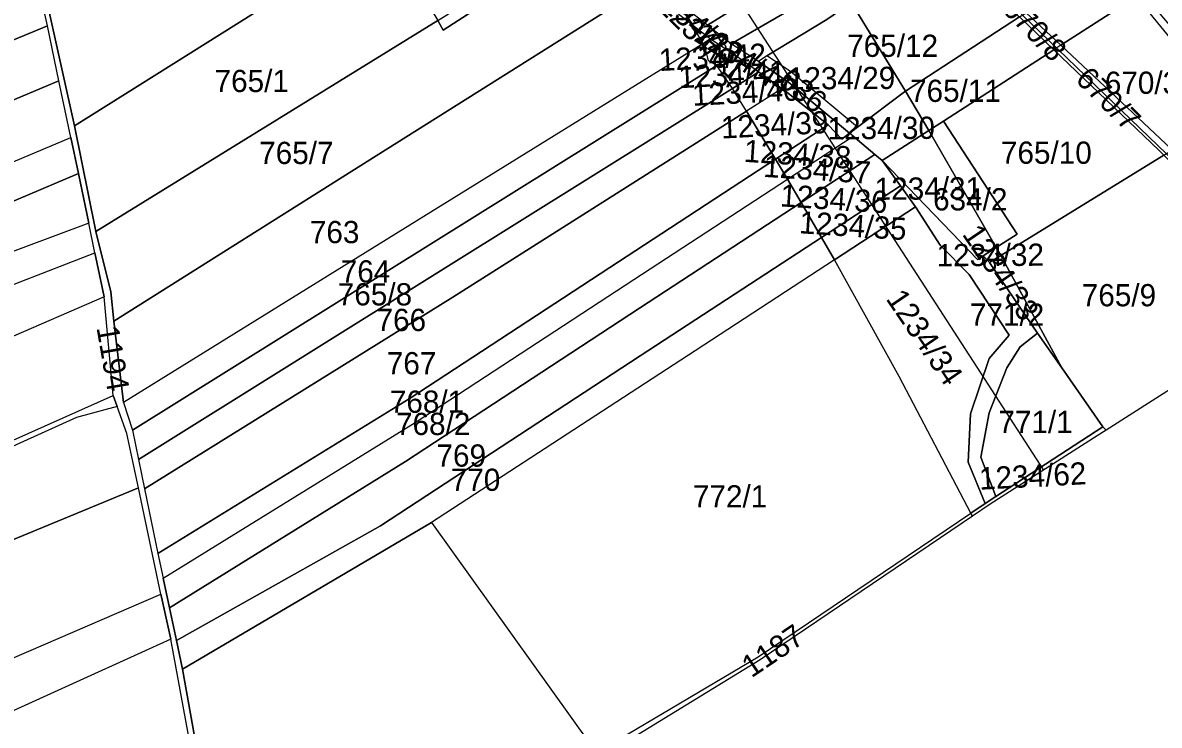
# Model space of a CAD drawing. Extents: x -623250 to -619626, y -1079612 to -1075424.
# Drawn here: x -620640 to -620129, y -1077297 to -1076980 of the extents above; entities that cross this region are included whole.
import ezdxf

# ---------------------------------------------------------------- set-up
doc = ezdxf.new("R2010")
doc.units = 0
for name, color, linetype in [('Dálnice a přivaděč', 7, 'Continuous'), ('Hranice převzatá (KoPÚ Hrušová)', 7, 'Continuous'), ('Parcela nároku', 7, 'Continuous'), ('Parcelní číslo', 7, 'Continuous'), ('Vodní toky', 7, 'Continuous')]:
    doc.layers.add(name, color=color, linetype=linetype)

msp = doc.modelspace()

# ---------------------------------------------------------------- linework, layer by layer
at = {"layer": 'Dálnice a přivaděč'}
msp.add_lwpolyline([(-621211.3, -1075762.42), (-621042.48, -1076053.84), (-620715.11, -1076495.7), (-620421.91, -1076809.46), (-620180.94, -1077181.74)], dxfattribs=at)
at = {"layer": 'Hranice převzatá (KoPÚ Hrušová)'}
msp.add_lwpolyline([(-620097.76, -1077128.63), (-620152.81, -1077163.77), (-620156.83, -1077166.34), (-620205.06, -1077197.13), (-620212.99, -1077202.5), (-620227.43, -1077212.27), (-620308.56, -1077267.13), (-620370.5, -1077305.13)], dxfattribs=at)
at = {"layer": 'Parcela nároku'}
for points in [[(-620119.98, -1076986.55), (-620149.91, -1076951.14), (-620165.48, -1076931.43), (-620186.12, -1076902.91), (-620210.08, -1076879.13), (-620234.82, -1076852.68), (-620272.81, -1076807.82), (-620281.18, -1076791.72), (-620287.52, -1076789.59), (-620286.26, -1076791.95), (-620275.61, -1076809.03), (-620263.77, -1076823.1), (-620250.84, -1076838.48), (-620237.34, -1076854.52), (-620222.38, -1076870.61), (-620212.62, -1076881.11), (-620205.93, -1076888.11), (-620198.43, -1076895.95), (-620188.91, -1076904.44), (-620182.36, -1076913.38), (-620153.45, -1076952.88), (-620139.36, -1076968.66), (-620122.17, -1076989.65)], [(-620564.8, -1077306.77), (-620573.82, -1077257.79), (-620578.2, -1077237.62), (-620588.31, -1077189.72), (-620593.55, -1077165.29), (-620597.96, -1077153.14), (-620599.73, -1077148.14), (-620603.79, -1077103.85), (-620607.96, -1077083.92), (-620610.74, -1077070.63), (-620615.34, -1077048.34), (-620618.82, -1077032.03), (-620624.13, -1077006.64), (-620629.28, -1076981.86), (-620643.85, -1076916.74)], [(-620640.94, -1076917.83), (-620636.67, -1076937.95), (-620632.74, -1076956.48), (-620617.09, -1077026.85), (-620607.45, -1077074.44), (-620600.78, -1077101.61), (-620599.35, -1077114.69), (-620595.04, -1077151.27), (-620591.05, -1077163.8), (-620588.33, -1077176.95), (-620585.6, -1077190.18), (-620579.59, -1077219.23), (-620577.16, -1077230.36), (-620574.34, -1077243.71), (-620571.27, -1077258.42), (-620568.57, -1077271.31), (-620559.44, -1077321.56)]]:
    msp.add_lwpolyline(points, dxfattribs=at)
for points in [[(-620512.67, -1076904.97), (-620482.96, -1076913.88), (-620449.74, -1076921.67), (-620477.8, -1076939.19), (-620617.09, -1077026.85), (-620632.74, -1076956.48), (-620522.79, -1076900.14)], [(-620629.28, -1076981.86), (-620643.85, -1076916.74), (-620738.29, -1076956.01), (-620832.54, -1076995.23), (-620921.02, -1077031.86), (-620904.58, -1077095.56), (-620767.08, -1077038.8)], [(-620617.09, -1077026.85), (-620477.8, -1076939.19), (-620453.59, -1076979.51), (-620607.45, -1077074.44)], [(-620342.24, -1076973.73), (-620293.41, -1076943.42), (-620287.71, -1076939.79), (-620281.35, -1076949.67), (-620288.1, -1076954.04), (-620332.29, -1076981.58)], [(-620607.45, -1077074.44), (-620453.59, -1076979.51), (-620451.23, -1076983.77), (-620392.48, -1076945.89), (-620362.83, -1076965.71), (-620481.3, -1077040.34), (-620599.35, -1077114.69), (-620600.78, -1077101.61)], [(-620396.89, -1076943.7), (-620392.48, -1076945.89), (-620451.23, -1076983.77), (-620453.59, -1076979.51)], [(-620382.24, -1076948.71), (-620389.9, -1076944.1), (-620392.48, -1076945.89), (-620362.83, -1076965.71), (-620345.66, -1076976.11), (-620338.99, -1076981.39), (-620344.75, -1076972.39), (-620353.32, -1076967.81), (-620362.93, -1076961.15)], [(-620192.55, -1076977.12), (-620191.78, -1076977.86), (-620243.08, -1077011.3), (-620265.18, -1076975.21), (-620267.16, -1076971.23), (-620227.5, -1076944.17)], [(-620332.29, -1076981.58), (-620288.1, -1076954.04), (-620281.24, -1076963.01), (-620290.67, -1076968.99), (-620294.62, -1076974.41), (-620321.62, -1076989.94), (-620329.63, -1076983.66)], [(-620188.81, -1076975.92), (-620153.45, -1076952.88), (-620139.36, -1076968.66), (-620173.21, -1076990.56)], [(-620281.24, -1076963.01), (-620275.25, -1076959.21), (-620268.09, -1076967.66), (-620267.16, -1076971.23), (-620278.53, -1076978.98), (-620305.51, -1076995.32), (-620309.3, -1076997.88), (-620321.62, -1076989.94), (-620294.62, -1076974.41), (-620290.67, -1076968.99)], [(-620345.66, -1076976.11), (-620338.99, -1076981.39), (-620334.37, -1076989.87), (-620463.09, -1077069.54), (-620595.04, -1077151.27), (-620599.35, -1077114.69), (-620481.3, -1077040.34), (-620362.83, -1076965.71)], [(-620267.16, -1076971.23), (-620265.18, -1076975.21), (-620243.08, -1077011.3), (-620243.56, -1077011.61), (-620264.75, -1077027.38), (-620294.86, -1077002.37), (-620305.51, -1076995.32), (-620278.53, -1076978.98)], [(-620173.21, -1076990.56), (-620139.36, -1076968.66), (-620122.17, -1076989.65), (-620096.52, -1077018.79), (-620097.72, -1077022.14), (-620123.12, -1077037.77), (-620125.94, -1077034.91)], [(-620332.29, -1076981.58), (-620342.24, -1076973.73), (-620344.75, -1076972.39), (-620338.99, -1076981.39), (-620330.95, -1076987.75), (-620323.84, -1076992.37), (-620324.09, -1076990.81), (-620326.28, -1076988.68), (-620329.63, -1076983.66)], [(-620191.78, -1076977.86), (-620188.81, -1076975.92), (-620173.21, -1076990.56), (-620176.37, -1076992.61)], [(-620767.08, -1077038.8), (-620904.58, -1077095.56), (-620896.8, -1077121.07), (-620760.56, -1077063.88), (-620624.13, -1077006.64), (-620629.28, -1076981.86)], [(-620338.99, -1076981.39), (-620330.95, -1076987.75), (-620334.37, -1076989.87)], [(-620191.78, -1076977.86), (-620176.37, -1076992.61), (-620226, -1077024.71), (-620232.57, -1077028.92), (-620243.08, -1077011.3)], [(-620309.3, -1076997.88), (-620321.62, -1076989.94), (-620329.63, -1076983.66), (-620326.28, -1076988.68), (-620324.09, -1076990.81), (-620323.84, -1076992.37), (-620320.13, -1076994.77), (-620309.18, -1077002.57), (-620298.69, -1077010), (-620277.89, -1077026.36), (-620271.7, -1077032.84), (-620268.29, -1077030.16), (-620295.56, -1077007.3)], [(-620328.09, -1076999.73), (-620331.71, -1076997.58), (-620332.93, -1076992.57), (-620334.37, -1076989.87), (-620463.09, -1077069.54), (-620595.04, -1077151.27), (-620591.05, -1077163.8), (-620455.63, -1077079.31)], [(-620330.95, -1076987.75), (-620323.84, -1076992.37), (-620320.13, -1076994.77), (-620328.09, -1076999.73), (-620331.71, -1076997.58), (-620332.93, -1076992.57), (-620334.37, -1076989.87)], [(-620129.14, -1077037.82), (-620126.86, -1077040.08), (-620200.22, -1077085.24), (-620202.26, -1077081.58), (-620192.92, -1077075.55), (-620226, -1077024.71), (-620176.37, -1076992.61)], [(-620123.12, -1077037.77), (-620125.94, -1077034.91), (-620173.21, -1076990.56), (-620176.37, -1076992.61), (-620129.14, -1077037.82), (-620126.86, -1077040.08)], [(-620320.13, -1076994.77), (-620309.18, -1077002.57), (-620321.03, -1077009.98), (-620328.09, -1076999.73)], [(-620294.86, -1077002.37), (-620305.51, -1076995.32), (-620309.3, -1076997.88), (-620295.56, -1077007.3), (-620268.29, -1077030.16), (-620264.75, -1077027.38)], [(-620321.03, -1077009.98), (-620328.09, -1076999.73), (-620455.63, -1077079.31), (-620591.05, -1077163.8), (-620588.33, -1077176.95), (-620448.79, -1077089.79)], [(-620309.18, -1077002.57), (-620298.69, -1077010), (-620314.75, -1077020.18), (-620321.03, -1077009.98)], [(-620618.82, -1077032.03), (-620624.13, -1077006.64), (-620760.56, -1077063.88), (-620896.8, -1077121.07), (-620889.38, -1077146.03), (-620754.08, -1077089.06)], [(-620314.75, -1077020.18), (-620321.03, -1077009.98), (-620448.79, -1077089.79), (-620588.33, -1077176.95), (-620585.6, -1077190.18), (-620446.91, -1077103.98)], [(-620298.69, -1077010), (-620314.75, -1077020.18), (-620301.62, -1077041.87), (-620277.89, -1077026.36)], [(-620264.75, -1077027.38), (-620243.56, -1077011.61), (-620243.08, -1077011.3), (-620232.57, -1077028.92), (-620253.65, -1077042.44), (-620256.95, -1077039.67), (-620266.72, -1077031.48), (-620268.29, -1077030.16)], [(-620301.62, -1077041.87), (-620314.75, -1077020.18), (-620446.91, -1077103.98), (-620585.6, -1077190.18), (-620579.59, -1077219.23), (-620466.48, -1077149.66), (-620372.28, -1077088.04)], [(-620266.72, -1077031.48), (-620268.29, -1077030.16), (-620271.7, -1077032.84), (-620277.89, -1077026.36), (-620301.62, -1077041.87), (-620296.29, -1077050.81)], [(-620226, -1077024.71), (-620192.92, -1077075.55), (-620202.26, -1077081.58), (-620232.57, -1077028.92)], [(-620754.08, -1077089.06), (-620618.82, -1077032.03), (-620615.34, -1077048.34), (-620749.99, -1077105.51), (-620884.45, -1077162.62), (-620889.38, -1077146.03)], [(-620296.29, -1077050.81), (-620266.72, -1077031.48), (-620256.95, -1077039.67), (-620290.07, -1077061.35)], [(-620232.57, -1077028.92), (-620202.26, -1077081.58), (-620208.17, -1077085.4), (-620210.68, -1077087.02), (-620253.65, -1077042.44)], [(-620372.28, -1077088.04), (-620466.48, -1077149.66), (-620579.59, -1077219.23), (-620577.16, -1077230.36), (-620463.85, -1077160.33), (-620365.38, -1077095.99), (-620296.29, -1077050.81), (-620301.62, -1077041.87)], [(-620253.65, -1077042.44), (-620245.42, -1077053.84), (-620280.93, -1077077.05), (-620290.07, -1077061.35), (-620256.95, -1077039.67)], [(-620209.16, -1077175.91), (-620202.47, -1077193.64), (-620207.32, -1077196.8), (-620214.93, -1077178.19), (-620213.83, -1077156.39), (-620205.39, -1077131.54), (-620196.45, -1077121.01), (-620214.46, -1077093.67), (-620227.44, -1077080.61), (-620238.56, -1077063.33), (-620245.42, -1077053.84), (-620253.65, -1077042.44), (-620210.68, -1077087.02), (-620208.17, -1077085.4), (-620205.31, -1077088.38), (-620183.7, -1077120.09), (-620191.44, -1077126.36), (-620197.51, -1077135.76), (-620205.53, -1077156.03)], [(-620200.22, -1077085.24), (-620126.86, -1077040.08), (-620117.98, -1077048.89), (-620113.77, -1077055.84), (-620110.49, -1077063.33), (-620092.57, -1077125.09), (-620097.76, -1077128.63), (-620152.81, -1077163.77), (-620154.24, -1077162.24), (-620172.79, -1077135.7)], [(-620749.99, -1077105.51), (-620615.34, -1077048.34), (-620610.74, -1077070.63), (-620670.29, -1077092.89), (-620734.88, -1077122.56), (-620878.33, -1077183.21), (-620884.45, -1077162.62)], [(-620463.85, -1077160.33), (-620365.38, -1077095.99), (-620296.29, -1077050.81), (-620290.07, -1077061.35), (-620362.78, -1077108.94), (-620468.2, -1077177.92), (-620574.34, -1077243.71), (-620577.16, -1077230.36)], [(-620280.93, -1077077.05), (-620245.42, -1077053.84), (-620238.56, -1077063.33), (-620275.1, -1077087.21)], [(-620362.78, -1077108.94), (-620290.07, -1077061.35), (-620280.93, -1077077.05), (-620362.52, -1077130.36), (-620479.43, -1077206.83), (-620571.27, -1077258.42), (-620574.34, -1077243.71), (-620468.2, -1077177.92)], [(-620214.46, -1077093.67), (-620196.45, -1077121.01), (-620205.39, -1077131.54), (-620213.83, -1077156.39), (-620214.93, -1077178.19), (-620207.32, -1077196.8), (-620213.7, -1077201.11), (-620245.94, -1077139.65), (-620275.1, -1077087.21), (-620238.56, -1077063.33), (-620227.44, -1077080.61)], [(-620670.29, -1077092.89), (-620734.88, -1077122.56), (-620878.33, -1077183.21), (-620874.52, -1077196.05), (-620780.25, -1077156.48), (-620665.33, -1077106.16), (-620607.96, -1077083.92), (-620610.74, -1077070.63)], [(-620479.43, -1077206.83), (-620362.52, -1077130.36), (-620280.93, -1077077.05), (-620275.1, -1077087.21), (-620337.73, -1077128.15), (-620456.45, -1077205.38), (-620568.57, -1077271.31), (-620571.27, -1077258.42)], [(-620665.33, -1077106.16), (-620607.96, -1077083.92), (-620603.79, -1077103.85), (-620780.87, -1077180.56), (-620868.37, -1077216.75), (-620874.52, -1077196.05), (-620780.25, -1077156.48)], [(-620208.17, -1077085.4), (-620202.26, -1077081.58), (-620200.22, -1077085.24), (-620205.31, -1077088.38)], [(-620213.7, -1077201.11), (-620245.94, -1077139.65), (-620275.1, -1077087.21), (-620337.73, -1077128.15), (-620456.45, -1077205.38), (-620384.64, -1077305.72), (-620422.26, -1077333.77), (-620371.95, -1077302.9), (-620309.42, -1077265.74)], [(-620205.31, -1077088.38), (-620200.22, -1077085.24), (-620172.79, -1077135.7), (-620183.7, -1077120.09)], [(-620603.79, -1077103.85), (-620780.87, -1077180.56), (-620868.37, -1077216.75), (-620861.9, -1077238.51), (-620854.18, -1077260.06), (-620841.88, -1077256.29), (-620720.81, -1077202.26), (-620599.73, -1077148.14)], [(-620191.44, -1077126.36), (-620183.7, -1077120.09), (-620172.79, -1077135.7), (-620154.24, -1077162.24), (-620202.47, -1077193.64), (-620209.16, -1077175.91), (-620205.53, -1077156.03), (-620197.51, -1077135.76)], [(-620854.18, -1077260.06), (-620841.88, -1077256.29), (-620720.81, -1077202.26), (-620599.73, -1077148.14), (-620597.96, -1077153.14), (-620616.17, -1077158.13), (-620729.34, -1077209.18), (-620842.44, -1077260.29), (-620852.88, -1077263.68)], [(-620729.34, -1077209.18), (-620842.44, -1077260.29), (-620852.88, -1077263.68), (-620839.03, -1077292.21), (-620783.8, -1077270.52), (-620686.15, -1077230.15), (-620588.31, -1077189.72), (-620593.55, -1077165.29), (-620597.96, -1077153.14), (-620616.17, -1077158.13)], [(-620154.24, -1077162.24), (-620152.81, -1077163.77), (-620156.83, -1077166.34), (-620205.06, -1077197.13), (-620212.99, -1077202.5), (-620213.25, -1077201.98), (-620213.7, -1077201.11), (-620207.32, -1077196.8), (-620202.47, -1077193.64)], [(-620686.15, -1077230.15), (-620783.8, -1077270.52), (-620839.03, -1077292.21), (-620824.5, -1077322.12), (-620818.03, -1077340.86), (-620698.27, -1077289.33), (-620578.2, -1077237.62), (-620588.31, -1077189.72)], [(-620213.7, -1077201.11), (-620213.25, -1077201.98), (-620212.99, -1077202.5), (-620227.43, -1077212.27), (-620308.56, -1077267.13), (-620370.5, -1077305.13), (-620371.95, -1077302.9), (-620309.42, -1077265.74)], [(-620456.45, -1077205.38), (-620384.64, -1077305.72), (-620422.26, -1077333.77), (-620462.8, -1077358.64), (-620524.9, -1077396.04), (-620539.81, -1077402.16), (-620543.64, -1077394.52), (-620559.44, -1077321.56), (-620568.57, -1077271.31)], [(-620698.27, -1077289.33), (-620578.2, -1077237.62), (-620573.82, -1077257.79), (-620688.76, -1077310.04), (-620812.33, -1077364.99), (-620818.03, -1077340.86)], [(-620564.8, -1077306.77), (-620573.82, -1077257.79), (-620688.76, -1077310.04), (-620812.33, -1077364.99), (-620813.72, -1077378.79), (-620674.53, -1077339)]]:
    msp.add_lwpolyline(points, close=True, dxfattribs=at)
at = {"layer": 'Vodní toky'}
msp.add_line((-620301.87, -1076869.58), (-620113.61, -1077051.07), dxfattribs=at)

# ---------------------------------------------------------------- texts
at = {"layer": 'Parcelní číslo'}
for s, rotation, p in [('1234/43', 320.3982, (-620359.52, -1076968.89)), ('1234/61', 315.7423, (-620355.39, -1076973.81)), ('670/8', 314.1231, (-620200.19, -1076974.68)), ('1234/44', 327.6745, (-620339.15, -1076988.04)), ('1234/42', 2.9794, (-620353.85, -1077002.2)), ('1234/41', 2.9794, (-620345.04, -1077009.94)), ('636', 321.6912, (-620301.13, -1077007.9)), ('1234/29', 0.2865, (-620296.04, -1077010.49)), ('670/7', 315.1259, (-620167.11, -1077006.4)), ('1234/40', 2.9794, (-620338.88, -1077017.88)), ('1234/39', 2.9794, (-620325.9, -1077032.59)), ('1234/30', 0.2865, (-620278.18, -1077032.95)), ('1234/38', 356.2652, (-620316.15, -1077043.02)), ('1234/37', 356.2652, (-620307.32, -1077049.79)), ('1234/36', 356.2652, (-620299.78, -1077063.07)), ('1234/31', 0.2865, (-620256.98, -1077060.17)), ('1234/35', 356.2652, (-620291.2, -1077075.17)), ('1234/33', 304.2979, (-620217.89, -1077075.63)), ('1234/32', 0.2865, (-620229.1, -1077090.06)), ('1234/34', 304.2979, (-620252.2, -1077104.72)), ('1194', 279.8366, (-620607.25, -1077117.65)), ('1234/62', 2.9794, (-620209.76, -1077190.62)), ('1187', 34.0533, (-620312.43, -1077275.5))]:
    msp.add_text(s, height=10, rotation=rotation, dxfattribs=at).set_placement(p)
for s, p in [('765/12', (-620269.36, -1076995.82)), ('765/1', (-620554.08, -1077011.65)), ('670/31', (-620153.42, -1077012.46)), ('765/11', (-620241.07, -1077016.08)), ('765/7', (-620534.01, -1077044.02)), ('765/10', (-620200.18, -1077043.92)), ('634/2', (-620230.7, -1077064.91)), ('763', (-620511.2, -1077079.65)), ('764', (-620497.29, -1077097.35)), ('765/8', (-620498.63, -1077107.66)), ('765/9', (-620163.78, -1077108.06)), ('766', (-620481.19, -1077119.18)), ('771/2', (-620214.14, -1077116.79)), ('767', (-620476.57, -1077138.67)), ('768/1', (-620475.21, -1077155.99)), ('768/2', (-620472.43, -1077165.98)), ('771/1', (-620201.32, -1077165.09)), ('769', (-620454.21, -1077180.21)), ('770', (-620447.78, -1077191.12)), ('772/1', (-620338.81, -1077198.57))]:
    msp.add_text(s, height=10, dxfattribs=at).set_placement(p)

doc.saveas('drawing.dxf')
